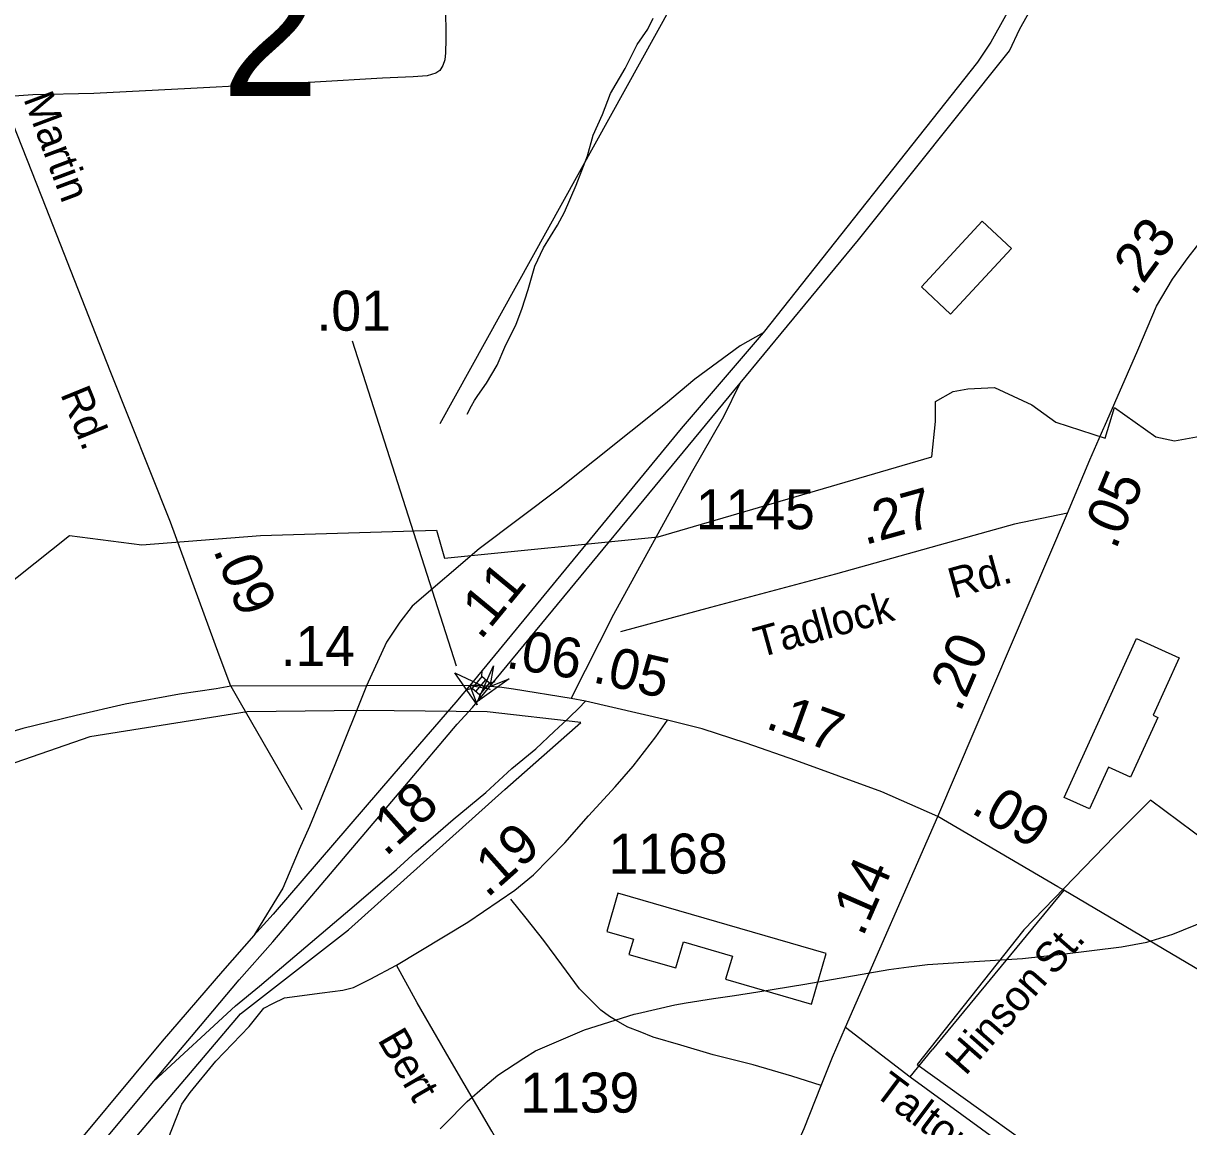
# Model space of a CAD drawing. Extents: x 2206922 to 2357709, y 510027 to 673830.
# Drawn here: x 2277190 to 2280832, y 532331 to 535777 of the extents above; entities that cross this region are included whole.
import ezdxf

# ---------------------------------------------------------------- set-up
doc = ezdxf.new("R2010")
doc.units = 0
for name, color, linetype in [('Exist Boundary Political City Limit New', 7, 'Continuous'), ('Exist Cultural Manufacturing Building Footprint', 7, 'Continuous'), ('Exist Cultural Warehouse Building Footprint', 7, 'Continuous'), ('Exist Hydrographic Creek Single Shore', 7, 'Continuous'), ('Exist Hydrographic Misc Water Feature', 7, 'Continuous'), ('Exist Road Non-System Type 51', 7, 'Continuous'), ('Exist Road Non-System Type 51 Label', 7, 'Continuous'), ('Exist Road Primary Interstate Ramp 1 Lane Attributed', 7, 'Continuous'), ('Exist Road Primary Interstate Structure Standard Bridge CELL', 7, 'Continuous'), ('Exist Road Primary NC Attributed', 7, 'Continuous'), ('Exist Road Primary NC Service Mileage Hundredths English Label', 7, 'Continuous'), ('Exist Road Primary US Attributed', 7, 'Continuous'), ('Exist Road Primary US Divided Attributed', 7, 'Continuous'), ('Exist Road Primary US Mileage Hundredths English Label', 7, 'Continuous'), ('Exist Road Primary US Ramp 1 Lane  Attributed', 7, 'Continuous'), ('Exist Road Primary US UnDivided 4 Lane Attributed', 7, 'Continuous'), ('Exist Road Secondary Mileage Hundredths English Label', 7, 'Continuous'), ('Exist Road Secondary Structure Standard Bridge Attributed CELL', 7, 'Continuous'), ('Exist Road Secondary Structure Standard Bridge Number Label', 7, 'Continuous'), ('Exist Road Secondary Type 51 Attributed', 7, 'Continuous'), ('Exist Road Secondary Type 51 Label', 7, 'Continuous'), ('Exist Road Secondary Type 51 Number Label', 7, 'Continuous'), ('Map Preparation Boundary City Limit Buffer Line', 7, 'Continuous')]:
    doc.layers.add(name, color=color, linetype=linetype)

msp = doc.modelspace()

# ---------------------------------------------------------------- linework, layer by layer
at = {"layer": 'Exist Boundary Political City Limit New'}
for points in [[(2276950.8, 533872.1), (2277335, 534176.7), (2277560.2, 534147.5), (2277931.2, 534176.7), (2278481.8, 534193.4), (2278506.8, 534105.8), (2279174, 534172.6), (2280028.8, 534422.9), (2280041, 534533.6), (2280040.2, 534595.6), (2280095.5, 534627.3), (2280141.5, 534635.6), (2280224.8, 534639.8), (2280341.5, 534585.6), (2280416.8, 534531.3), (2280571, 534481.2), (2280600.2, 534577.2), (2280729.5, 534485.4), (2280787.8, 534472.9), (2280879.5, 534489.6)], [(2282560, 533751.1), (2282457.8, 533617.3), (2282413.2, 533571.7), (2282189, 533313.7), (2282162.5, 533328.2), (2281863.8, 532954.2), (2281651, 533150.4), (2281213.2, 533442.4), (2281071.2, 533083.6), (2280712.8, 533350.6), (2280600.2, 533238), (2280316.5, 532945.9), (2279983, 532524.6), (2281542.5, 531406.4), (2281125.5, 530843.2), (2282080.5, 530839), (2282230.8, 530359.2), (2282818.5, 530313.3)], [(2276259.2, 530784.8), (2277868.8, 532683.1), (2278206.5, 532945.9), (2278694.5, 533384), (2278932.2, 533592.6), (2278640.2, 533626), (2278252.5, 533630.2), (2277889.8, 533626), (2277397.8, 533548.4), (2276513.5, 533242.1)]]:
    msp.add_lwpolyline(points, dxfattribs=at)
at = {"layer": 'Exist Cultural Manufacturing Building Footprint'}
for p, q in [((2280442.6, 533359.1), (2280668.7, 533855.3)), ((2280668.7, 533855.3), (2280801.9, 533794.6)), ((2280801.9, 533794.6), (2280720.3, 533615.5)), ((2280720.3, 533615.5), (2280735.1, 533608.8)), ((2280735.1, 533608.8), (2280650.3, 533422.7)), ((2280581.6, 533454), (2280521.9, 533323)), ((2280650.3, 533422.7), (2280581.6, 533454)), ((2280521.9, 533323), (2280442.6, 533359.1)), ((2279047.9, 533059.6), (2279013.4, 532940.1)), ((2279699.1, 532871.4), (2279047.9, 533059.6)), ((2279013.4, 532940.1), (2279096.5, 532916.1)), ((2279096.5, 532916.1), (2279082.8, 532868.9)), ((2279229.3, 532826.5), (2279252.8, 532907.9)), ((2279252.8, 532907.9), (2279405.8, 532863.7)), ((2279082.8, 532868.9), (2279229.3, 532826.5)), ((2279405.8, 532863.7), (2279384.9, 532791.5)), ((2279653.6, 532713.8), (2279699.1, 532871.4)), ((2279384.9, 532791.5), (2279653.6, 532713.8))]:
    msp.add_line(p, q, dxfattribs=at)
at = {"layer": 'Exist Cultural Warehouse Building Footprint'}
for p, q in [((2280186.9, 535158.7), (2279996.5, 534953.8)), ((2280278.2, 535073.9), (2280186.9, 535158.7)), ((2280087.9, 534868.9), (2280278.2, 535073.9)), ((2279996.5, 534953.8), (2280087.9, 534868.9))]:
    msp.add_line(p, q, dxfattribs=at)
at = {"layer": 'Exist Hydrographic Creek Single Shore'}
msp.add_lwpolyline([(2278492.8, 534526.4), (2279361, 536093), (2279385, 536233.5), (2279373.9, 536519), (2279270, 536957.3), (2279223.8, 537450.2), (2279247.8, 537531.7), (2279451.8, 537983.5), (2279673.9, 538320.1), (2279746.9, 538554.7), (2279753.9, 538695.6), (2279809.9, 538937.2), (2279874.9, 539103.1), (2280054.9, 539371.7), (2280127.9, 539622.7), (2280157.8, 539989.4), (2280167.9, 540655), (2280164.8, 540669.7)], dxfattribs=at)
at = {"layer": 'Exist Hydrographic Misc Water Feature'}
for p, q in [((2279099, 532681.8), (2279109.4, 532684.2)), ((2278493, 532323.6), (2278506.8, 532337.7))]:
    msp.add_line(p, q, dxfattribs=at)
for points in [[(2278577.1, 534556), (2278590.8, 534582.3), (2278600.3, 534598.3), (2278610.1, 534614.3), (2278637.8, 534652.7), (2278671.4, 534708.8), (2278695.2, 534765.3), (2278730.3, 534837.5), (2278747.7, 534883.5), (2278767.4, 534945.8), (2278788.7, 535018), (2278815.8, 535076), (2278859.5, 535146.5), (2278881, 535186.6), (2278917.9, 535271), (2278953.4, 535363.1), (2278970.8, 535427.3), (2278999.7, 535491.5), (2279025.3, 535557.8), (2279070.7, 535636.1), (2279108, 535710.4), (2279141.6, 535758.8), (2279158.6, 535792.7)], [(2280161.9, 532846.4), (2280312, 532855.7), (2280435.9, 532869.5), (2280621.9, 532892.8), (2280701, 532907.3), (2280782, 532931.5), (2280887, 532974.9), (2280924.1, 532993.3)], [(2280161.9, 532846.4), (2280312, 532855.7), (2280435.9, 532869.5), (2280621.9, 532892.8), (2280701, 532907.3), (2280782, 532931.5), (2280887, 532974.9), (2280924.1, 532993.3)], [(2279956.9, 532829.9), (2280015.9, 532837.5), (2280161.9, 532846.4)], [(2279956.9, 532829.9), (2280015.9, 532837.5), (2280161.9, 532846.4)], [(2279631.9, 532775.5), (2279895, 532822), (2279956.9, 532829.9)], [(2279631.9, 532775.5), (2279895, 532822), (2279956.9, 532829.9)], [(2279412.5, 532740.8), (2279485.9, 532751.7), (2279631.9, 532775.5)], [(2279412.5, 532740.8), (2279485.9, 532751.7), (2279631.9, 532775.5)], [(2279261.6, 532717.2), (2279346.9, 532731.4), (2279412.5, 532740.8)], [(2279261.6, 532717.2), (2279346.9, 532731.4), (2279412.5, 532740.8)], [(2279109.4, 532684.2), (2279225.9, 532711.3), (2279261.6, 532717.2)], [(2279109.4, 532684.2), (2279225.9, 532711.3), (2279261.6, 532717.2)], [(2278754.5, 532544.2), (2278791, 532567.6), (2278943.9, 532633.6), (2279099, 532681.8)], [(2278754.5, 532544.2), (2278791, 532567.6), (2278943.9, 532633.6), (2279099, 532681.8)], [(2278632.5, 532457.1), (2278672.9, 532491.8), (2278754.5, 532544.2)], [(2278632.5, 532457.1), (2278672.9, 532491.8), (2278754.5, 532544.2)], [(2278506.8, 532337.7), (2278576.9, 532409.3), (2278632.5, 532457.1)], [(2278506.8, 532337.7), (2278576.9, 532409.3), (2278632.5, 532457.1)]]:
    msp.add_lwpolyline(points, dxfattribs=at)
at = {"layer": 'Exist Road Non-System Type 51'}
for p, q in [((2277838.4, 533706.4), (2277867.5, 533656)), ((2277867.5, 533656), (2278060.5, 533321.7)), ((2280441.5, 533069), (2280030.2, 532570.5)), ((2279961.1, 532486.7), (2280030.2, 532570.5))]:
    msp.add_line(p, q, dxfattribs=at)
for points in [[(2278509.2, 535811.5), (2278511, 535748.9), (2278510.1, 535727.8), (2278509.3, 535684.6), (2278507.4, 535662.8), (2278501.4, 535644.9), (2278491.5, 535629.1), (2278479.6, 535621.1), (2278451.8, 535613.2), (2278408.2, 535609.2), (2278313, 535605.3), (2278100.9, 535593.4), (2277910.5, 535583.4), (2277714.2, 535573.5), (2277410.9, 535557.7), (2277220.5, 535553.7), (2277161.6, 535549.2), (2277127.7, 535541.4)], [(2279683.8, 532459.5), (2279591.8, 532488.7), (2279470.8, 532523.9), (2279346.2, 532555.4), (2279244.5, 532585.3), (2279158.5, 532609.9), (2279118.2, 532627.4), (2279079.6, 532641.4), (2279048, 532659), (2279021.7, 532674.8), (2278995.4, 532694.1), (2278969.1, 532720.4), (2278928.7, 532760.8), (2278872.6, 532836.3), (2278816.5, 532911.7), (2278762.1, 532982), (2278713.3, 533041.2)]]:
    msp.add_lwpolyline(points, dxfattribs=at)
at = {"layer": 'Exist Road Primary Interstate Ramp 1 Lane Attributed'}
msp.add_lwpolyline([(2277598.3, 532473.2), (2277853.6, 532707.6), (2277928.8, 532769.2), (2278231.9, 533026.9)], dxfattribs=at)
at = {"layer": 'Exist Road Primary Interstate Structure Standard Bridge CELL'}
for p, q in [((2278623, 533736.3), (2278624.4, 533755.1)), ((2278604.6, 533689.8), (2278635.1, 533726.2)), ((2278647, 533716.2), (2278665.2, 533720.9)), ((2278574.2, 533695.2), (2278592.4, 533699.9)), ((2278615.2, 533660.9), (2278616.7, 533679.6))]:
    msp.add_line(p, q, dxfattribs=at)
msp.add_lwpolyline([(2278616.7, 533679.6), (2278647.2, 533716), (2278622.9, 533736.3), (2278592.4, 533699.9)], close=True, dxfattribs=at)
at = {"layer": 'Exist Road Primary NC Attributed'}
msp.add_line((2279203, 533600.8), (2278947, 533659.8), dxfattribs=at)
for points in [[(2277838.4, 533706.4), (2277793, 533698.6), (2277678.7, 533681.7), (2277508.5, 533650.5), (2277355.2, 533615.4), (2277189, 533573.8), (2277031.8, 533527), (2276677.2, 533399.7), (2276309.7, 533264.5), (2275942.1, 533128), (2275623.9, 533008.5), (2275232.9, 532865.5), (2274717.3, 532671.9), (2274421.3, 532564.4)], [(2278262.9, 533707.6), (2277838.4, 533706.4)], [(2278585.2, 533708.6), (2278262.9, 533707.6)], [(2278648.4, 533705.8), (2278614.7, 533708.6), (2278585.2, 533708.6)], [(2278902.3, 533667.7), (2278721.8, 533696.8), (2278685.3, 533702.7), (2278648.4, 533705.8)], [(2278947, 533659.8), (2278902.3, 533667.7)], [(2280047.5, 533299.2), (2279873.3, 533376.8), (2279604.7, 533474.2), (2279449.2, 533528.4), (2279311.1, 533572.8), (2279203, 533600.8)], [(2282085.1, 532073.2), (2281536, 532405.1), (2281396.2, 532494.2), (2281063.1, 532701.5), (2280441.5, 533069), (2280422.4, 533080.2), (2280047.5, 533299.2)]]:
    msp.add_lwpolyline(points, dxfattribs=at)
at = {"layer": 'Exist Road Primary NC Service Mileage Hundredths English Label'}
msp.add_line((2278543.5, 533768.7), (2278219.1, 534784.5), dxfattribs=at)
at = {"layer": 'Exist Road Primary US Attributed'}
msp.add_lwpolyline([(2280453.1, 534247.1), (2280522.9, 534413.4), (2280566.7, 534513.4), (2280568.6, 534517.7), (2280672.9, 534755.5), (2280731.3, 534892.9), (2280780.9, 534978.1), (2280830.5, 535045.5), (2280882.6, 535111.6), (2281030.1, 535298.6), (2281149.2, 535445.6), (2281196.6, 535499.5)], dxfattribs=at)
at = {"layer": 'Exist Road Primary US Divided Attributed'}
for points in [[(2281123.2, 543168.4), (2280963.1, 542286.2), (2280889.6, 541750.5), (2280839.6, 541200), (2280786.6, 540225.7), (2280721.9, 538730.5), (2280668.9, 537559), (2280645.4, 537093.9), (2280624.8, 536905.5), (2280605.1, 536752.5), (2280579, 536616.1), (2280539, 536445.7), (2280451.7, 536191.7), (2280360.9, 535984.7), (2280213.6, 535718), (2280172.2, 535655.7), (2279502, 534810.1)], [(2279430.3, 534652.5), (2279800, 535100.2), (2280271.8, 535691.3), (2280304.5, 535759.9), (2280414.7, 535956.4), (2280518.9, 536179), (2280609.1, 536421.6), (2280657.2, 536602.1), (2280683.3, 536734.5), (2280710.1, 536879), (2280755.9, 537091), (2280761.4, 537542.5), (2280813.1, 538724.6), (2280851.3, 539451.6), (2280880.8, 540222.8), (2280924.9, 541173.5), (2280974.9, 541724), (2281042.5, 542200.8), (2281205.4, 543126.5)], [(2279502, 534810.1), (2279246.3, 534511.1), (2278585.2, 533708.6)], [(2278648.4, 533705.8), (2279430.3, 534652.5)], [(2277598.3, 532473.2), (2277653, 532538.9), (2277744.1, 532646.1), (2277864.9, 532789.7), (2277969.8, 532908.3), (2278382.4, 533394.1), (2278546.5, 533588), (2278594.3, 533640.4), (2278648.4, 533705.8)], [(2278585.2, 533708.6), (2278541.4, 533656.3), (2278509, 533617.8), (2278348.2, 533432.9), (2277970.7, 532994.9), (2277910.3, 532928.3)], [(2277910.3, 532928.3), (2277812.4, 532816.5), (2277624.7, 532597.6), (2277279.2, 532183.1), (2276928.9, 531771.8), (2276597.5, 531381.8), (2276324.1, 531049.6), (2275975.4, 530630), (2275315.9, 529858.2)], [(2275360.2, 529823.2), (2275418.9, 529892.9), (2276005, 530582.1), (2276217, 530830.7), (2276367.4, 531013.1), (2276659.2, 531364.3), (2276980.6, 531738.4), (2277345.3, 532169.4), (2277598.3, 532473.2)]]:
    msp.add_lwpolyline(points, dxfattribs=at)
at = {"layer": 'Exist Road Primary US Ramp 1 Lane  Attributed'}
for points in [[(2279502, 534810.1), (2279430.7, 534769), (2279289.1, 534665.4), (2279197, 534588.8), (2278866.3, 534324.8), (2278614.8, 534135.9), (2278404.9, 533956.7), (2278367.3, 533906.5), (2278324.7, 533843.8), (2278262.9, 533707.6)], [(2278902.3, 533667.7), (2279035.4, 533931.6), (2279278.6, 534373.1), (2279378.9, 534548.7), (2279430.3, 534652.5)], [(2278262.9, 533707.6), (2278163.4, 533460.7), (2278084.6, 533268.6), (2278052.2, 533196), (2278001.3, 533076.1), (2277910.3, 532928.3)]]:
    msp.add_lwpolyline(points, dxfattribs=at)
at = {"layer": 'Exist Road Primary US UnDivided 4 Lane Attributed'}
for p, q in [((2280047.5, 533299.2), (2280453.1, 534247.1)), ((2279759.2, 532641.3), (2280047.5, 533299.2))]:
    msp.add_line(p, q, dxfattribs=at)
msp.add_lwpolyline([(2279414.3, 531015.9), (2279416.6, 531356.6), (2279419, 531470.9), (2279428.5, 531607.4), (2279433.2, 531694.1), (2279460.8, 531859.6), (2279500.6, 532004.6), (2279549.5, 532141.9), (2279629.8, 532325.3), (2279683.8, 532459.5), (2279719.2, 532547.7), (2279759.2, 532641.3)], dxfattribs=at)
at = {"layer": 'Exist Road Secondary Structure Standard Bridge Attributed CELL'}
for points in [[(2278708.7, 533729.9), (2278609.9, 533658.5), (2278659.8, 533769.8), (2278648.4, 533705.8)], [(2278608.5, 533647.9), (2278538.5, 533747.7), (2278649, 533696.3), (2278585.2, 533708.6)]]:
    msp.add_lwpolyline(points, close=True, dxfattribs=at)
at = {"layer": 'Exist Road Secondary Type 51 Attributed'}
for points in [[(2277838.4, 533706.4), (2277802, 533803.8), (2277650.3, 534218.8), (2277461.7, 534691.4), (2277261.7, 535200.8), (2277127.7, 535541.4), (2276996.8, 535874), (2276918.8, 536124.8), (2276895.5, 536279.1), (2276888.6, 536391), (2276889.4, 536502.9), (2276898.7, 536792.8), (2276911.2, 537166.8), (2276938.3, 537864.9), (2276946.1, 538105.4), (2276951.3, 538241.8)], [(2280453.1, 534247.1), (2280287.8, 534212.5), (2280051.8, 534146.5), (2279727.9, 534056.5), (2279338, 533952.5), (2279056.1, 533876.5)], [(2278231.9, 533026.9), (2278356, 533134.1), (2278416.8, 533189.2), (2278533.7, 533289.7), (2278635.2, 533374.8), (2278717.3, 533448.9), (2278791.5, 533510.8), (2278849.3, 533565.2), (2278890, 533602.5), (2278897.1, 533609.5), (2278925.8, 533637.7), (2278947, 533659.8)], [(2278356, 532834.8), (2278579.2, 532969.3), (2278726.2, 533068.9), (2278785, 533117.5), (2278882.3, 533217.2), (2278956.7, 533301.3), (2279039.4, 533391.9), (2279095.8, 533456.9), (2279166.3, 533548.7), (2279203, 533600.8)], [(2277173, 531801.8), (2277262.3, 531851.5), (2277307.3, 531874.8), (2277343.8, 531910.5), (2277644.6, 532298.4), (2277666.2, 532350.5), (2277685.6, 532400.7), (2277711.3, 532437), (2277792.3, 532535.7), (2277896.4, 532643.6), (2277942, 532700.4), (2277969.6, 532715.4), (2278006.6, 532732.7), (2278124.1, 532748.5), (2278188.8, 532757.1), (2278221.9, 532765.8), (2278274, 532791.8), (2278356, 532834.8)], [(2279414.3, 531015.9), (2279201.4, 531360.5), (2279073.6, 531584.5), (2278921.4, 531853.4), (2278769.2, 532116), (2278654.1, 532317.1), (2278520.8, 532544.2), (2278421.4, 532717.7), (2278356, 532834.8)], [(2279759.2, 532641.3), (2279961.1, 532486.7), (2281499.1, 531366), (2281536, 531340.6)]]:
    msp.add_lwpolyline(points, dxfattribs=at)
at = {"layer": 'Map Preparation Boundary City Limit Buffer Line'}
for points in [[(2276950.8, 533872.1), (2277335, 534176.7), (2277560.2, 534147.5), (2277931.2, 534176.7), (2278481.8, 534193.4), (2278506.8, 534105.8), (2279174, 534172.6), (2280028.8, 534422.9), (2280041, 534533.6), (2280040.2, 534595.6), (2280095.5, 534627.3), (2280141.5, 534635.6), (2280224.8, 534639.8), (2280341.5, 534585.6), (2280416.8, 534531.3), (2280571, 534481.2), (2280600.2, 534577.2), (2280729.5, 534485.4), (2280787.8, 534472.9), (2280879.5, 534489.6)], [(2282560, 533751.1), (2282457.8, 533617.3), (2282413.2, 533571.7), (2282189, 533313.7), (2282162.5, 533328.2), (2281863.8, 532954.2), (2281651, 533150.4), (2281213.2, 533442.4), (2281071.2, 533083.6), (2280712.8, 533350.6), (2280600.2, 533238), (2280316.5, 532945.9), (2279983, 532524.6), (2281542.5, 531406.4), (2281125.5, 530843.2), (2282080.5, 530839), (2282230.8, 530359.2), (2282818.5, 530313.3)], [(2276259.2, 530784.8), (2277868.8, 532683.1), (2278206.5, 532945.9), (2278694.5, 533384), (2278932.2, 533592.6), (2278640.2, 533626), (2278252.5, 533630.2), (2277889.8, 533626), (2277397.8, 533548.4), (2276513.5, 533242.1)]]:
    msp.add_lwpolyline(points, dxfattribs=at)

# ---------------------------------------------------------------- texts
at = {"layer": 'Exist Road Non-System Type 51 Label'}
for s, p in [('St.', (2280410.6, 532799)), ('Hinson', (2280134.3, 532487.1))]:
    msp.add_text(s, height=95, rotation=48.7792, dxfattribs=at).set_placement(p)
at = {"layer": 'Exist Road Primary NC Service Mileage Hundredths English Label'}
for s, rotation, p in [('.01', 0.1693, (2278106.6, 534816.4)), ('.14', 0.1688, (2277994.5, 533769.3)), ('.06', 350.8408, (2278695, 533764.4)), ('.05', 347.0306, (2278965.5, 533719.7)), ('.17', 340.0631, (2279505.6, 533576.7)), ('.09', 329.7069, (2280147.5, 533313.2))]:
    msp.add_text(s, height=125, rotation=rotation, dxfattribs=at).set_placement(p)
at = {"layer": 'Exist Road Primary US Mileage Hundredths English Label'}
for s, rotation, p in [('.23', 53.6678, (2280661.9, 534921.7)), ('.05', 67.2333, (2280603.7, 534129.9)), ('.11', 50.5215, (2278618.9, 533847.7)), ('.20', 66.8321, (2280117.5, 533621.7)), ('.14', 66.3426, (2279813.4, 532920.7))]:
    msp.add_text(s, height=125, rotation=rotation, dxfattribs=at).set_placement(p)
at = {"layer": 'Exist Road Secondary Mileage Hundredths English Label'}
for s, rotation, p in [('.27', 15.5312, (2279819.8, 534146.9)), ('.09', 291.9697, (2277782.6, 534131.8)), ('.18', 41.7008, (2278322.3, 533171.9)), ('.19', 41.7008, (2278639.7, 533042.5))]:
    msp.add_text(s, height=125, rotation=rotation, dxfattribs=at).set_placement(p)
at = {"layer": 'Exist Road Secondary Structure Standard Bridge Number Label'}
msp.add_text('2', height=410.1, dxfattribs=at).set_placement((2277810.1, 535549.4))
at = {"layer": 'Exist Road Secondary Type 51 Label'}
for s, rotation, p in [('Martin', 290.5111, (2277189.8, 535541.6)), ('Rd.', 292.1799, (2277305, 534619.3)), ('Rd.', 15.4542, (2280095.6, 533979.6)), ('Tadlock', 15.4542, (2279489.1, 533794.8)), ('Bert', 300.0003, (2278295.6, 532602.4)), ('Talton', 323.0186, (2279842.7, 532432.4))]:
    msp.add_text(s, height=95, rotation=rotation, dxfattribs=at).set_placement(p)
at = {"layer": 'Exist Road Secondary Type 51 Number Label'}
for s, p in [('1145', (2279291.7, 534196.5)), ('1168', (2279019.1, 533121)), ('1139', (2278743.2, 532374.6))]:
    msp.add_text(s, height=125, dxfattribs=at).set_placement(p)

doc.saveas('drawing.dxf')
